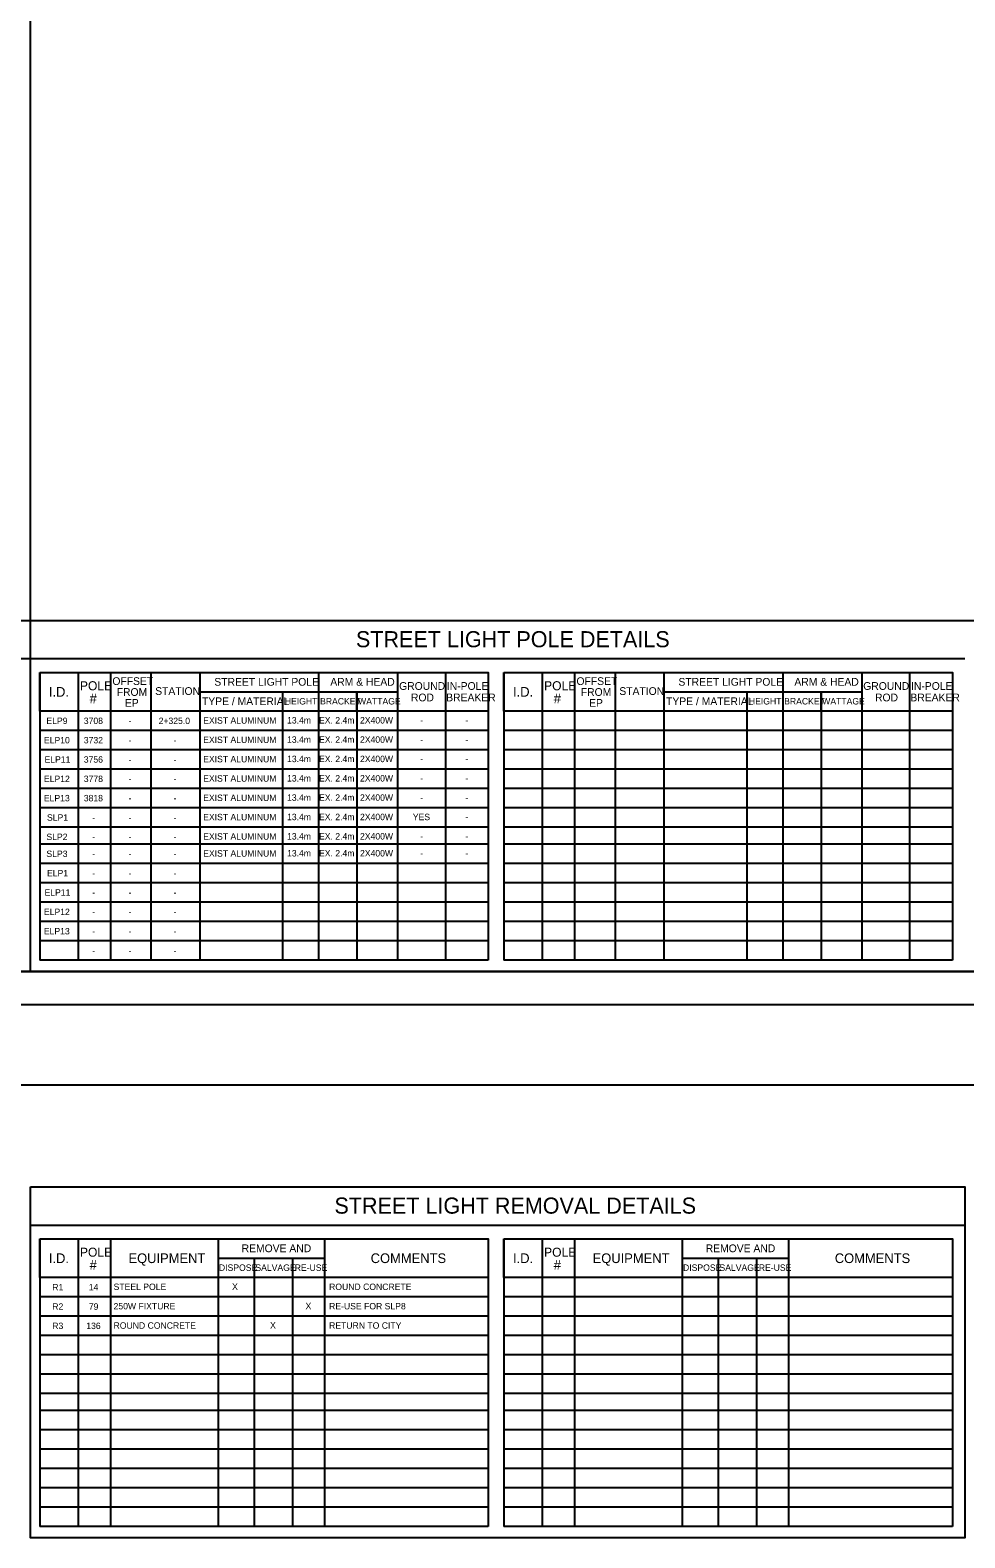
# Model space of a CAD drawing. Extents: x 602909 to 603631, y 4846273 to 4846729.
# Drawn here: x 603054.8 to 603194.8, y 4846272.8 to 4846498.6 of the extents above; entities that cross this region are included whole.
import ezdxf

# ---------------------------------------------------------------- set-up
doc = ezdxf.new("R2010")
doc.units = 0
for name, color, linetype in [('-PRINT FULLSIZE', 7, 'Continuous'), ('-PRINT HALFSIZE', 7, 'Continuous'), ('ENG_BORDER', 7, 'Continuous'), ('ENG_TITLEBLOCK', 7, 'Continuous'), ('ENG_TX_TITLEBLOCK', 7, 'Continuous'), ('SL - Border Text', 7, 'Continuous')]:
    doc.layers.add(name, color=color, linetype=linetype)

msp = doc.modelspace()

# ---------------------------------------------------------------- linework, layer by layer
at = {"layer": '-PRINT FULLSIZE'}
msp.add_lwpolyline([(602930, 4846340.65), (603377.03, 4846340.65), (603377.03, 4846645.65), (602930, 4846645.65)], close=True, dxfattribs=at)
at = {"layer": '-PRINT HALFSIZE'}
msp.add_lwpolyline([(602959.8, 4846631.64), (603368.72, 4846631.64), (603368.72, 4846352.64), (602959.8, 4846352.64)], close=True, dxfattribs=at)
at = {"layer": 'ENG_BORDER'}
for p, q in [((603054.8, 4846357.64), (603054.8, 4846626.86)), ((602977.52, 4846410.23), (603363.74, 4846410.23)), ((602977.52, 4846404.5), (603194.76, 4846404.5)), ((603363.72, 4846357.64), (602977.52, 4846357.64)), ((603054.8, 4846319.66), (603194.76, 4846319.66))]:
    msp.add_line(p, q, dxfattribs=at)
for points in [[(602977.52, 4846357.64), (603363.72, 4846357.64), (603363.72, 4846626.64), (602977.52, 4846626.64)], [(603054.8, 4846325.39), (603194.76, 4846325.39), (603194.76, 4846272.8), (603054.8, 4846272.8)]]:
    msp.add_lwpolyline(points, close=True, dxfattribs=at)
at = {"layer": 'ENG_TITLEBLOCK'}
for p, q in [((603056.19, 4846402.44), (603056.19, 4846359.34)), ((603061.96, 4846402.44), (603061.96, 4846359.34)), ((603061.96, 4846402.44), (603061.96, 4846396.64)), ((603066.79, 4846402.44), (603066.79, 4846359.34)), ((603080.19, 4846402.44), (603080.19, 4846359.34)), ((603097.96, 4846402.44), (603097.96, 4846359.34)), ((603109.8, 4846402.44), (603109.8, 4846359.34)), ((603116.97, 4846402.44), (603116.97, 4846359.34)), ((603123.38, 4846402.44), (603123.38, 4846359.34)), ((603125.71, 4846402.44), (603125.71, 4846359.34)), ((603131.47, 4846402.44), (603131.47, 4846359.34)), ((603131.47, 4846402.44), (603131.47, 4846396.64)), ((603136.31, 4846402.44), (603136.31, 4846359.34)), ((603149.7, 4846402.44), (603149.7, 4846359.34)), ((603167.48, 4846402.44), (603167.48, 4846359.34)), ((603179.31, 4846402.44), (603179.31, 4846359.34)), ((603186.49, 4846402.44), (603186.49, 4846359.34)), ((603192.89, 4846402.44), (603192.89, 4846359.34)), ((603080.19, 4846399.54), (603109.8, 4846399.54)), ((603092.57, 4846399.54), (603092.57, 4846359.34)), ((603103.7, 4846399.54), (603103.7, 4846359.34)), ((603103.7, 4846396.64), (603103.7, 4846399.54)), ((603149.7, 4846399.54), (603179.31, 4846399.54)), ((603162.09, 4846399.54), (603162.09, 4846359.34)), ((603173.22, 4846399.54), (603173.22, 4846359.34)), ((603173.22, 4846396.64), (603173.22, 4846399.54)), ((603123.38, 4846393.75), (603056.19, 4846393.75)), ((603192.89, 4846393.75), (603125.71, 4846393.75)), ((603123.38, 4846390.85), (603056.19, 4846390.85)), ((603192.89, 4846390.85), (603125.71, 4846390.85)), ((603123.38, 4846387.95), (603056.19, 4846387.95)), ((603192.89, 4846387.95), (603125.71, 4846387.95)), ((603123.38, 4846385.06), (603056.19, 4846385.06)), ((603192.89, 4846385.06), (603125.71, 4846385.06)), ((603123.38, 4846382.16), (603056.19, 4846382.16)), ((603192.89, 4846382.16), (603125.71, 4846382.16)), ((603116.81, 4846379.26), (603056.19, 4846379.26)), ((603123.38, 4846379.26), (603100.06, 4846379.26)), ((603192.89, 4846379.26), (603125.72, 4846379.26)), ((603123.38, 4846376.72), (603056.19, 4846376.72)), ((603192.89, 4846376.72), (603125.71, 4846376.72)), ((603123.38, 4846373.82), (603056.19, 4846373.83)), ((603192.89, 4846373.82), (603125.71, 4846373.83)), ((603123.38, 4846370.93), (603056.19, 4846370.93)), ((603192.89, 4846370.93), (603125.71, 4846370.93)), ((603123.38, 4846368.03), (603056.19, 4846368.03)), ((603192.89, 4846368.03), (603125.71, 4846368.03)), ((603123.38, 4846365.14), (603056.19, 4846365.14)), ((603192.89, 4846365.14), (603125.71, 4846365.14)), ((603123.38, 4846362.24), (603056.19, 4846362.24)), ((603192.89, 4846362.24), (603125.71, 4846362.24)), ((603123.38, 4846359.34), (603056.19, 4846359.34)), ((603192.89, 4846359.34), (603125.71, 4846359.34)), ((603056.19, 4846317.59), (603056.19, 4846274.5)), ((603061.96, 4846317.59), (603061.96, 4846274.5)), ((603066.79, 4846317.59), (603066.79, 4846274.5)), ((603082.92, 4846317.59), (603082.92, 4846274.5)), ((603098.85, 4846317.59), (603098.85, 4846274.5)), ((603123.38, 4846317.59), (603123.38, 4846274.5)), ((603125.71, 4846317.59), (603125.71, 4846274.5)), ((603131.47, 4846317.59), (603131.47, 4846274.5)), ((603136.31, 4846317.59), (603136.31, 4846274.5)), ((603152.43, 4846317.59), (603152.43, 4846274.5)), ((603168.36, 4846317.59), (603168.36, 4846274.5)), ((603192.89, 4846317.59), (603192.89, 4846274.5)), ((603082.92, 4846314.7), (603098.85, 4846314.7)), ((603088.31, 4846314.7), (603088.31, 4846274.5)), ((603094.05, 4846314.7), (603094.05, 4846274.5)), ((603152.43, 4846314.7), (603168.36, 4846314.7)), ((603157.82, 4846314.7), (603157.82, 4846274.5)), ((603163.56, 4846314.7), (603163.56, 4846274.5)), ((603123.38, 4846308.9), (603056.19, 4846308.9)), ((603192.89, 4846308.9), (603125.71, 4846308.9)), ((603123.38, 4846306.01), (603056.19, 4846306.01)), ((603192.89, 4846306.01), (603125.71, 4846306.01)), ((603123.38, 4846303.11), (603056.19, 4846303.11)), ((603192.89, 4846303.11), (603125.71, 4846303.11)), ((603123.38, 4846300.21), (603056.19, 4846300.21)), ((603192.89, 4846300.21), (603125.71, 4846300.21)), ((603123.38, 4846297.32), (603056.19, 4846297.32)), ((603192.89, 4846297.32), (603125.71, 4846297.32)), ((603123.38, 4846294.42), (603056.19, 4846294.42)), ((603192.89, 4846294.42), (603125.71, 4846294.42)), ((603123.38, 4846291.88), (603056.19, 4846291.88)), ((603192.89, 4846291.88), (603125.71, 4846291.88)), ((603123.38, 4846288.98), (603056.19, 4846288.98)), ((603192.89, 4846288.98), (603125.71, 4846288.98)), ((603123.38, 4846286.09), (603056.19, 4846286.09)), ((603192.89, 4846286.09), (603125.71, 4846286.09)), ((603123.38, 4846283.19), (603056.19, 4846283.19)), ((603192.89, 4846283.19), (603125.71, 4846283.19)), ((603123.38, 4846280.29), (603056.19, 4846280.29)), ((603192.89, 4846280.29), (603125.71, 4846280.29)), ((603123.38, 4846277.4), (603056.19, 4846277.4)), ((603192.89, 4846277.4), (603125.71, 4846277.4)), ((603123.38, 4846274.5), (603056.19, 4846274.5)), ((603192.89, 4846274.5), (603125.71, 4846274.5))]:
    msp.add_line(p, q, dxfattribs=at)
for points in [[(603056.19, 4846402.44), (603123.38, 4846402.44), (603123.38, 4846396.64), (603056.19, 4846396.64)], [(603125.71, 4846402.44), (603192.89, 4846402.44), (603192.89, 4846396.64), (603125.71, 4846396.64)], [(603056.19, 4846317.59), (603123.38, 4846317.59), (603123.38, 4846311.8), (603056.19, 4846311.8)], [(603125.71, 4846317.59), (603192.89, 4846317.59), (603192.89, 4846311.8), (603125.71, 4846311.8)]]:
    msp.add_lwpolyline(points, close=True, dxfattribs=at)
at = {"layer": 'SL - Border Text'}
for p, q in [((603056.19, 4846402.44), (603123.38, 4846402.44)), ((603072.86, 4846402.44), (603072.86, 4846359.34)), ((603109.8, 4846402.44), (603109.8, 4846396.64)), ((603116.97, 4846402.44), (603116.97, 4846396.64)), ((603125.71, 4846402.44), (603192.89, 4846402.44)), ((603142.37, 4846402.44), (603142.37, 4846359.34)), ((603179.31, 4846402.44), (603179.31, 4846396.64)), ((603186.49, 4846402.44), (603186.49, 4846396.64)), ((603123.38, 4846396.64), (603056.19, 4846396.64)), ((603192.89, 4846396.64), (603125.71, 4846396.64)), ((603056.19, 4846317.59), (603123.38, 4846317.59)), ((603061.96, 4846317.59), (603061.96, 4846317.59)), ((603125.71, 4846317.59), (603192.89, 4846317.59)), ((603082.92, 4846314.7), (603098.85, 4846314.7)), ((603152.43, 4846314.7), (603168.36, 4846314.7)), ((603123.38, 4846311.8), (603056.19, 4846311.8)), ((603192.89, 4846311.8), (603125.71, 4846311.8))]:
    msp.add_line(p, q, dxfattribs=at)

# ---------------------------------------------------------------- texts
at = {"layer": 'ENG_TX_TITLEBLOCK'}
for s, height, rotation, p in [('STREET LIGHT POLE DETAILS', 2.4137, 360, (603103.56, 4846406.2)), ('POLE', 1.352, 359.9999, (603062.22, 4846399.76)), ('OFFSET', 1.159, 359.9999, (603067.08, 4846400.55)), ('STREET LIGHT POLE', 1.1586, 359.9999, (603082.35, 4846400.44)), ('ARM & HEAD', 1.159, 359.9999, (603099.72, 4846400.44)), ('GROUND', 1.159, 359.9999, (603110.03, 4846399.82)), ('IN-POLE', 1.159, 359.9999, (603117.18, 4846399.82)), ('POLE', 1.352, 359.9999, (603131.74, 4846399.76)), ('OFFSET', 1.159, 359.9999, (603136.59, 4846400.55)), ('STREET LIGHT POLE', 1.1586, 359.9999, (603151.86, 4846400.44)), ('ARM & HEAD', 1.159, 359.9999, (603169.23, 4846400.44)), ('GROUND', 1.159, 359.9999, (603179.54, 4846399.82)), ('IN-POLE', 1.159, 359.9999, (603186.7, 4846399.82)), ('I.D.', 1.448, 359.9999, (603057.57, 4846398.8)), ('#', 1.45, 359.9999, (603063.68, 4846397.81)), ('FROM', 1.159, 359.9999, (603067.73, 4846398.92)), ('STATION', 1.159, 359.9999, (603073.49, 4846399.06)), ('TYPE / MATERIAL', 1.1586, 359.9999, (603080.5, 4846397.53)), ('ROD', 1.159, 359.9999, (603111.8, 4846398.1)), ('BREAKER', 1.159, 359.9999, (603117.08, 4846398.1)), ('I.D.', 1.448, 359.9999, (603127.09, 4846398.8)), ('#', 1.45, 359.9999, (603133.19, 4846397.81)), ('FROM', 1.159, 359.9999, (603137.24, 4846398.92)), ('STATION', 1.159, 359.9999, (603143.01, 4846399.06)), ('TYPE / MATERIAL', 1.1586, 359.9999, (603150.01, 4846397.53)), ('ROD', 1.159, 359.9999, (603181.31, 4846398.1)), ('BREAKER', 1.159, 359.9999, (603186.6, 4846398.1)), ('EP', 1.159, 359.9999, (603068.96, 4846397.29)), ('HEIGHT', 0.965, 359.9999, (603092.91, 4846397.63)), ('BRACKET', 0.965, 359.9999, (603098.19, 4846397.63)), ('WATTAGE', 0.965, 359.9999, (603103.88, 4846397.63)), ('EP', 1.159, 359.9999, (603138.48, 4846397.29)), ('HEIGHT', 0.965, 359.9999, (603162.42, 4846397.63)), ('BRACKET', 0.965, 359.9999, (603167.7, 4846397.63)), ('WATTAGE', 0.965, 359.9999, (603173.4, 4846397.63)), ('ELP9', 0.965, 359.9999, (603057.2, 4846394.7)), ('3708', 0.965, 359.9999, (603062.8, 4846394.7)), ('-', 0.965, 359.9999, (603069.52, 4846394.7)), ('2+325.0', 0.965, 359.9999, (603074.01, 4846394.7)), ('EXIST ALUMINUM', 0.9655, 359.9999, (603080.68, 4846394.76)), ('13.4m', 0.965, 359.9999, (603093.24, 4846394.78)), ('EX. 2.4m', 0.965, 359.9999, (603098.03, 4846394.78)), ('2X400W', 0.965, 359.9999, (603104.17, 4846394.78)), ('-', 0.965, 359.9999, (603113.19, 4846394.78)), ('-', 0.965, 359.9999, (603119.95, 4846394.78)), ('ELP10', 0.965, 359.9999, (603056.83, 4846391.8)), ('3732', 0.965, 359.9999, (603062.8, 4846391.8)), ('-', 0.965, 359.9999, (603069.52, 4846391.8)), ('-', 0.965, 359.9999, (603076.23, 4846391.8)), ('EXIST ALUMINUM', 0.9655, 359.9999, (603080.68, 4846391.86)), ('13.4m', 0.965, 359.9999, (603093.24, 4846391.89)), ('EX. 2.4m', 0.965, 359.9999, (603098.03, 4846391.89)), ('2X400W', 0.965, 359.9999, (603104.17, 4846391.89)), ('-', 0.965, 359.9999, (603113.19, 4846391.89)), ('-', 0.965, 359.9999, (603119.95, 4846391.89)), ('ELP11', 0.965, 359.9999, (603056.92, 4846388.91)), ('3756', 0.965, 359.9999, (603062.8, 4846388.91)), ('EXIST ALUMINUM', 0.9655, 359.9999, (603080.68, 4846388.97)), ('13.4m', 0.965, 359.9999, (603093.24, 4846388.99)), ('EX. 2.4m', 0.965, 359.9999, (603098.03, 4846388.99)), ('2X400W', 0.965, 359.9999, (603104.17, 4846388.99)), ('-', 0.965, 359.9999, (603069.52, 4846388.91)), ('-', 0.965, 359.9999, (603076.23, 4846388.91)), ('-', 0.965, 359.9999, (603113.19, 4846388.99)), ('-', 0.965, 359.9999, (603119.95, 4846388.99)), ('ELP12', 0.965, 359.9999, (603056.83, 4846386.01)), ('3778', 0.965, 359.9999, (603062.8, 4846386.01)), ('-', 0.965, 359.9999, (603069.52, 4846386.01)), ('-', 0.965, 359.9999, (603076.23, 4846386.01)), ('EXIST ALUMINUM', 0.9655, 359.9999, (603080.68, 4846386.07)), ('13.4m', 0.965, 359.9999, (603093.24, 4846386.09)), ('EX. 2.4m', 0.965, 359.9999, (603098.03, 4846386.09)), ('2X400W', 0.965, 359.9999, (603104.17, 4846386.09)), ('-', 0.965, 359.9999, (603113.19, 4846386.09)), ('-', 0.965, 359.9999, (603119.95, 4846386.09)), ('ELP13', 0.965, 359.9999, (603056.82, 4846383.12)), ('3818', 0.965, 359.9999, (603062.8, 4846383.12)), ('-', 0.965, 359.9999, (603069.52, 4846383.12)), ('-', 0.965, 359.9999, (603076.23, 4846383.12)), ('EXIST ALUMINUM', 0.9655, 359.9999, (603080.68, 4846383.17)), ('13.4m', 0.965, 359.9999, (603093.24, 4846383.2)), ('EX. 2.4m', 0.965, 359.9999, (603098.03, 4846383.2)), ('2X400W', 0.965, 359.9999, (603104.17, 4846383.2)), ('-', 0.965, 359.9999, (603113.19, 4846383.2)), ('-', 0.965, 359.9999, (603119.95, 4846383.2)), ('SLP1', 0.965, 359.9999, (603057.29, 4846380.22)), ('-', 0.965, 359.9999, (603064.06, 4846380.22)), ('-', 0.965, 359.9999, (603069.52, 4846380.22)), ('-', 0.965, 359.9999, (603076.23, 4846380.22)), ('EXIST ALUMINUM', 0.9655, 359.9999, (603080.68, 4846380.28)), ('13.4m', 0.965, 359.9999, (603093.24, 4846380.3)), ('EX. 2.4m', 0.965, 359.9999, (603098.03, 4846380.3)), ('2X400W', 0.965, 359.9999, (603104.17, 4846380.3)), ('YES', 0.965, 359.9999, (603112.08, 4846380.3)), ('-', 0.965, 359.9999, (603119.95, 4846380.3)), ('13.4m', 0.965, 359.9999, (603093.24, 4846377.4)), ('EX. 2.4m', 0.965, 359.9999, (603098.03, 4846377.4)), ('2X400W', 0.965, 359.9999, (603104.17, 4846377.4)), ('SLP2', 0.965, 359.9999, (603057.2, 4846377.32)), ('-', 0.965, 359.9999, (603064.06, 4846377.32)), ('-', 0.965, 359.9999, (603069.52, 4846377.32)), ('-', 0.965, 359.9999, (603076.23, 4846377.32)), ('EXIST ALUMINUM', 0.9655, 359.9999, (603080.68, 4846377.38)), ('-', 0.965, 359.9999, (603113.19, 4846377.4)), ('-', 0.965, 359.9999, (603119.95, 4846377.4)), ('SLP3', 0.965, 359.9999, (603057.2, 4846374.78)), ('-', 0.965, 359.9999, (603064.06, 4846374.78)), ('-', 0.965, 359.9999, (603069.52, 4846374.78)), ('-', 0.965, 359.9999, (603076.23, 4846374.78)), ('EXIST ALUMINUM', 0.9655, 359.9999, (603080.68, 4846374.84)), ('13.4m', 0.965, 359.9999, (603093.24, 4846374.86)), ('EX. 2.4m', 0.965, 359.9999, (603098.03, 4846374.86)), ('2X400W', 0.965, 359.9999, (603104.17, 4846374.86)), ('-', 0.965, 359.9999, (603113.19, 4846374.86)), ('-', 0.965, 359.9999, (603119.95, 4846374.86)), ('ELP1', 0.965, 359.9999, (603057.29, 4846371.88)), ('-', 0.965, 359.9999, (603064.06, 4846371.88)), ('-', 0.965, 359.9999, (603069.52, 4846371.88)), ('-', 0.965, 359.9999, (603076.23, 4846371.88)), ('ELP11', 0.965, 359.9999, (603056.92, 4846368.99)), ('-', 0.965, 359.9999, (603064.06, 4846368.99)), ('-', 0.965, 359.9999, (603069.52, 4846368.99)), ('-', 0.965, 359.9999, (603076.23, 4846368.99)), ('ELP12', 0.965, 359.9999, (603056.83, 4846366.09)), ('-', 0.965, 359.9999, (603064.06, 4846366.09)), ('-', 0.965, 359.9999, (603069.52, 4846366.09)), ('-', 0.965, 359.9999, (603076.23, 4846366.09)), ('ELP13', 0.965, 359.9999, (603056.82, 4846363.19)), ('-', 0.965, 359.9999, (603064.06, 4846363.19)), ('-', 0.965, 359.9999, (603069.52, 4846363.19)), ('-', 0.965, 359.9999, (603076.23, 4846363.19)), ('-', 0.965, 359.9999, (603064.06, 4846360.3)), ('-', 0.965, 359.9999, (603069.52, 4846360.3)), ('-', 0.965, 359.9999, (603076.23, 4846360.3)), ('STREET LIGHT REMOVAL DETAILS', 2.4137, 360, (603100.34, 4846321.36)), ('I.D.', 1.448, 359.9999, (603057.57, 4846313.96)), ('POLE', 1.352, 359.9999, (603062.22, 4846314.91)), ('EQUIPMENT', 1.448, 359.9999, (603069.49, 4846313.96)), ('REMOVE AND', 1.159, 359.9999, (603086.44, 4846315.59)), ('COMMENTS', 1.448, 359.9999, (603105.77, 4846313.96)), ('I.D.', 1.448, 359.9999, (603127.09, 4846313.96)), ('POLE', 1.352, 359.9999, (603131.74, 4846314.91)), ('EQUIPMENT', 1.448, 359.9999, (603139.01, 4846313.96)), ('REMOVE AND', 1.159, 359.9999, (603155.95, 4846315.59)), ('COMMENTS', 1.448, 359.9999, (603175.28, 4846313.96)), ('#', 1.45, 359.9999, (603063.68, 4846312.97)), ('DISPOSE', 0.965, 359.9999, (603083.04, 4846312.79)), ('SALVAGE', 0.965, 359.9999, (603088.5, 4846312.79)), ('RE-USE', 0.965, 359.9999, (603094.39, 4846312.79)), ('#', 1.45, 359.9999, (603133.19, 4846312.97)), ('DISPOSE', 0.965, 359.9999, (603152.55, 4846312.79)), ('SALVAGE', 0.965, 359.9999, (603158.01, 4846312.79)), ('RE-USE', 0.965, 359.9999, (603163.9, 4846312.79)), ('R1', 0.965, 359.9999, (603058.08, 4846309.86)), ('14', 0.965, 359.9999, (603063.55, 4846309.86)), ('STEEL POLE', 0.965, 359.9999, (603067.26, 4846309.92)), ('X', 0.965, 359.9999, (603085.01, 4846309.94)), ('ROUND CONCRETE', 0.9655, 359.9999, (603099.54, 4846309.92)), ('R2', 0.965, 359.9999, (603058.08, 4846306.96)), ('79', 0.965, 359.9999, (603063.55, 4846306.96)), ('250W FIXTURE', 0.9655, 359.9999, (603067.26, 4846307.02)), ('X', 0.965, 359.9999, (603096.01, 4846307.04)), ('RE-USE FOR SLP8', 0.9655, 359.9999, (603099.54, 4846307.02)), ('R3', 0.965, 359.9999, (603058.08, 4846304.07)), ('136', 0.965, 359.9999, (603063.17, 4846304.07)), ('ROUND CONCRETE', 0.9655, 359.9999, (603067.26, 4846304.12)), ('X', 0.965, 359.9999, (603090.7, 4846304.15)), ('RETURN TO CITY', 0.9655, 359.9999, (603099.54, 4846304.12))]:
    msp.add_text(s, height=height, rotation=rotation, dxfattribs=at).set_placement(p)

doc.saveas('drawing.dxf')
